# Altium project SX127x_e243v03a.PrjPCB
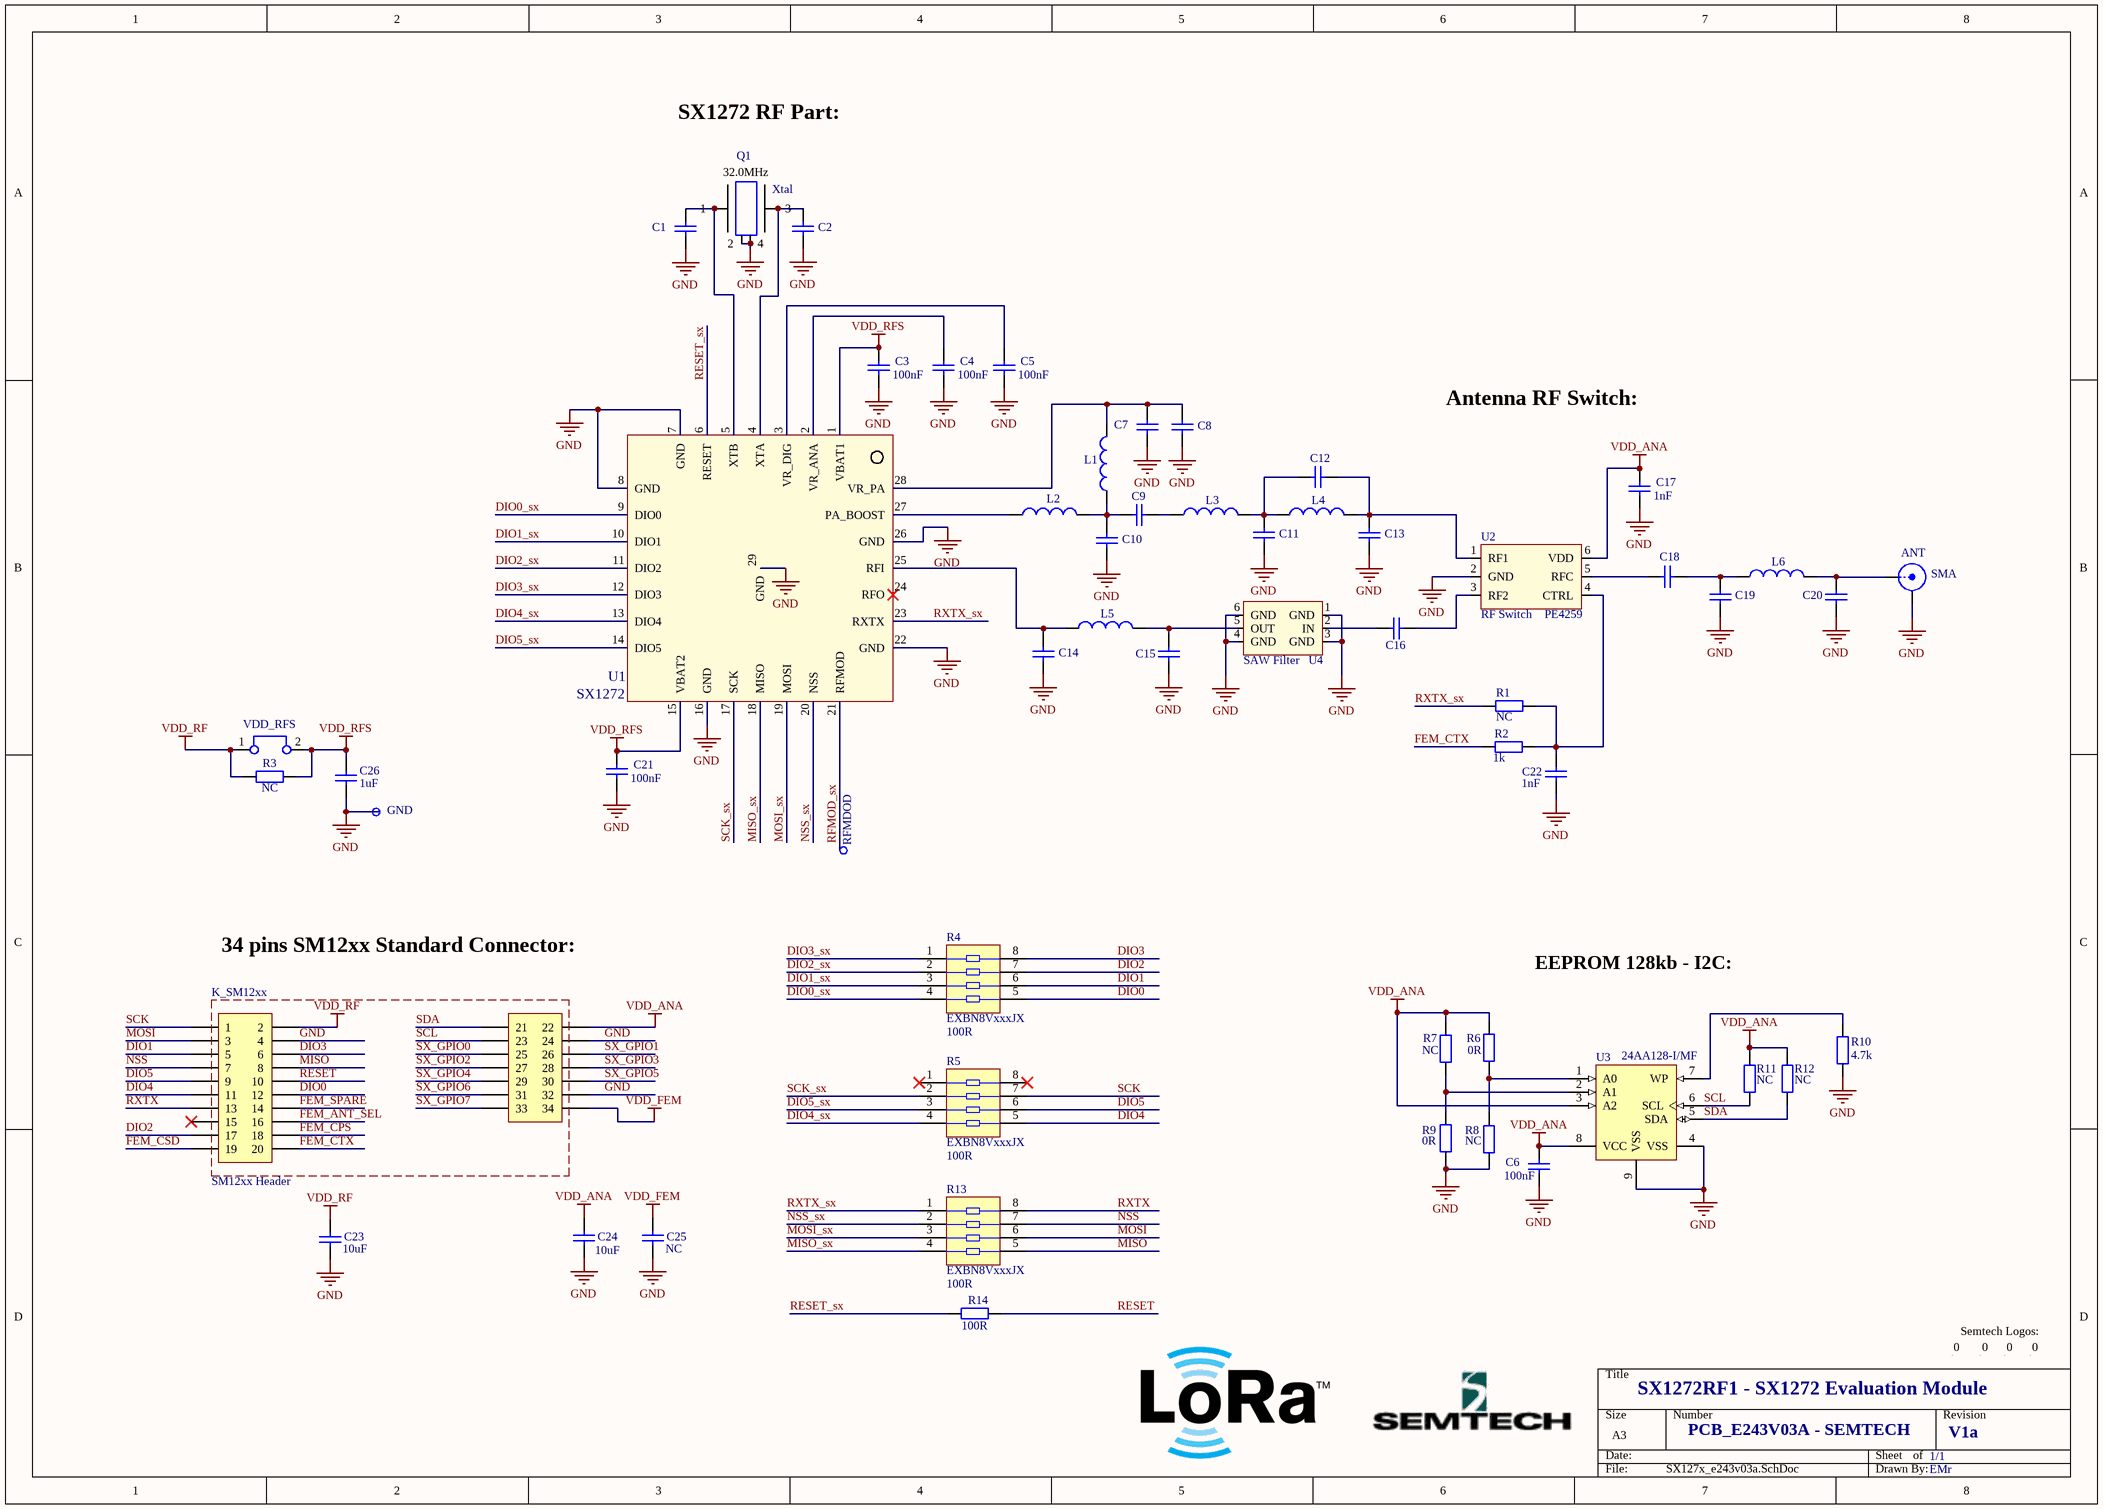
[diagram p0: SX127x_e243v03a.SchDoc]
1 sheet, 60 parts. Net scope: global (net labels, ports and power ports of the same name join across sheets).
Board file: SX127x_e243v03a.PcbDoc

## Sheet SX127x_e243v03a.SchDoc
size A3

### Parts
ANT  SMA  [SMA END LAUNCH JACK RECEPTACLE SHORT]
C1  Cap  [rlc_402_smd]  (value not drawn)
C2  Cap  [rlc_402_smd]  (value not drawn)
C3  value 100nF  [rlc_402_smd]  (hidden comment: Cap)
C4  value 100nF  [rlc_402_smd]  (hidden comment: Cap)
C5  value 100nF  [rlc_402_smd]  (hidden comment: Cap)
C6  value 100nF  [rlc_402_smd]  (hidden comment: Cap)
C7  Cap  [rlc_402_smd]  (value not drawn)
C8  Cap  [rlc_402_smd]  (value not drawn)
C9  Cap  [rlc_402_smd]  (value not drawn)
C10  Cap  [rlc_402_smd]  (value not drawn)
C11  Cap  [rlc_402_smd]  (value not drawn)
C12  Cap  [rlc_402_smd]  (value not drawn)
C13  Cap  [rlc_402_smd]  (value not drawn)
C14  Cap  [rlc_402_smd]  (value not drawn)
C15  Cap  [rlc_402_smd]  (value not drawn)
C16  Cap  [rlc_402_smd]  (value not drawn)
C17  value 1nF  [rlc_402_smd]  (hidden comment: Cap)
C18  Cap  [rlc_402_smd]  (value not drawn)
C19  Cap  [rlc_402_smd]  (value not drawn)
C20  Cap  [rlc_402_smd]  (value not drawn)
C21  value 100nF  [rlc_402_smd]  (hidden comment: Cap)
C22  value 1nF  [rlc_402_smd]  (hidden comment: Cap)
C23  value 10uF  [rlc_805_smd]  (hidden comment: Cap)
C24  value 10uF  [rlc_805_smd]  (hidden comment: Cap)
C25  value NC  [rlc_805_smd]  (hidden comment: Cap)
C26  value 1uF  [rlc_603_smd]  (hidden comment: Cap Semi)
GND  Test Pin  [pin_1mm]  (value not drawn)
K_SM12xx  SM12xx Header  [HDR34 Header]
L1  Inductor  [rlc_402_smd]  (value not drawn)
L2  Inductor  [rlc_402_smd]  (value not drawn)
L3  Inductor  [rlc_402_smd]  (value not drawn)
L4  Inductor  [rlc_402_smd]  (value not drawn)
L5  Inductor  [rlc_402_smd]  (value not drawn)
L6  Inductor  [rlc_402_smd]  (value not drawn)
Logo_Bot  Logo symbol  [logo_semtech_horiz_size3]  (value not drawn)
Logo_Lora_Bot  Logo symbol  [Logo LoRa Size4]  (value not drawn)
Logo_Lora_Top  Logo symbol  [Logo LoRa Size2]  (value not drawn)
Logo_Top  Logo symbol  [logo_semtech_horiz_size2]  (value not drawn)
Q1  Xtal  value 32.0MHz  [nd3225da - nd2520da]
R1  value NC  [rlc_402_smd]  (hidden comment: Resistor)
R2  value 1k  [rlc_402_smd]  (hidden comment: Resistor)
R3  value NC  [rlc_805_smd]  (hidden comment: Resistor)
R4  EXBN8VxxxJX  value 100R  [EXB28V]
R5  EXBN8VxxxJX  value 100R  [EXB28V]
R6  value 0R  [rlc_402_smd]  (hidden comment: Resistor)
R7  value NC  [rlc_402_smd]  (hidden comment: Resistor)
R8  value NC  [rlc_402_smd]  (hidden comment: Resistor)
R9  value 0R  [rlc_402_smd]  (hidden comment: Resistor)
R10  value 4.7k  [rlc_402_smd]  (hidden comment: Resistor)
R11  value NC  [rlc_402_smd]  (hidden comment: Resistor)
R12  value NC  [rlc_402_smd]  (hidden comment: Resistor)
R13  EXBN8VxxxJX  value 100R  [EXB28V]
R14  value 100R  [rlc_402_smd]  (hidden comment: Resistor)
RFMDOD  Test Pin  [pin_0.9mm]  (value not drawn)
U1  SX1272  [vqfn28_6x6mm]
U2  RF Switch  value PE4259  [SC70-6]
U3  24AA128-I/MF  [DFN8_ 5x6mm]
U4  SAW Filter  [DCC6C_3.0x3.0mm]
VDD_RFS  Jumper  [bridge_254mm]  (value not drawn)

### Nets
GND: ANT.2(GND) C1.1 C2.1 C3.1 C4.1 C5.1 C6.1 C7.1 C8.1 C10.1 C11.1 C13.1 C14.1 C15.1 C17.1 C19.1 C20.1 C21.1 C22.2 C23.1 C24.1 C25.2 C26.1 GND.1(pin) K_SM12xx.4 K_SM12xx.24 K_SM12xx.32 Q1.2 Q1.4 R8.1 R9.1 R10.1 U1.7(GND) U1.8(GND) U1.16(GND) U1.22(GND) U1.26(GND) U1.29(GND) U2.2(GND) U3.4(VSS) U3.9(VSS) U4.1(GND) U4.3(GND) U4.4(GND) U4.6(GND)
VDD_ANA: C6.2 C17.2 C24.2 K_SM12xx.22 R6.2 R7.2 R11.2 R12.2 U2.6(VDD) U3.3(A2) U3.8(VCC)
VDD_FEM: C25.1 K_SM12xx.34
VDD_RF: C23.2 K_SM12xx.2 R3.2 VDD_RFS.1
VDD_RFS: C3.2 C21.2 C26.2 R3.1 U1.1(VBAT1) U1.15(VBAT2) VDD_RFS.2
DIO0: K_SM12xx.12 R4.5
DIO0_sx: R4.4 U1.9(DIO0)
DIO1: K_SM12xx.5 R4.6
DIO1_sx: R4.3 U1.10(DIO1)
DIO2: K_SM12xx.17 R4.7
DIO2_sx: R4.2 U1.11(DIO2)
DIO3: K_SM12xx.6 R4.8
DIO3_sx: R4.1 U1.12(DIO3)
DIO4: K_SM12xx.11 R5.5
DIO4_sx: R5.4 U1.13(DIO4)
DIO5: K_SM12xx.9 R5.6
DIO5_sx: R5.3 U1.14(DIO5)
FEM_ANT_SEL: K_SM12xx.16
FEM_CPS: K_SM12xx.18
FEM_CSD: K_SM12xx.19
FEM_CTX: K_SM12xx.20 R2.2
FEM_SPARE: K_SM12xx.14
MISO: K_SM12xx.8 R13.5
MISO_sx: R13.4 U1.18(MISO)
MOSI: K_SM12xx.3 R13.6
MOSI_sx: R13.3 U1.19(MOSI)
NSS: K_SM12xx.7 R13.7
NSS_sx: R13.2 U1.20(NSS)
RESET: K_SM12xx.10 R14.2
RESET_sx: R14.1 U1.6(RESET)
RFMOD_sx: RFMDOD.1(pin) U1.21(RFMOD)
RXTX: K_SM12xx.13 R13.8
RXTX_sx: R1.1 R13.1 U1.23(RXTX)
SCK: K_SM12xx.1 R5.7
SCK_sx: R5.2 U1.17(SCK)
SCL: K_SM12xx.23 R11.1 U3.6(SCL)
SDA: K_SM12xx.21 R12.1 U3.5(SDA)
SX_GPIO0: K_SM12xx.25
SX_GPIO1: K_SM12xx.26
SX_GPIO2: K_SM12xx.27
SX_GPIO3: K_SM12xx.28
SX_GPIO4: K_SM12xx.29
SX_GPIO5: K_SM12xx.30
SX_GPIO6: K_SM12xx.31
SX_GPIO7: K_SM12xx.33
NetANT_1: ANT.1(Signal) C20.2 L6.2
NetC1_2: C1.2 Q1.1 U1.5(XTB)
NetC2_2: C2.2 Q1.3 U1.4(XTA)
NetC4_2: C4.2 U1.2(VR_ANA)
NetC5_2: C5.2 U1.3(VR_DIG)
NetC7_2: C7.2 C8.2 L1.2 U1.28(VR_PA)
NetC9_1: C9.1 L3.1
NetC9_2: C9.2 C10.2 L1.1 L2.2
NetC11_2: C11.2 C12.2 L3.2 L4.1
NetC12_1: C12.1 C13.2 L4.2 U2.1(RF1)
NetC14_2: C14.2 L5.1 U1.25(RFI)
NetC15_2: C15.2 L5.2 U4.5(OUT)
NetC16_1: C16.1 U2.3(RF2)
NetC16_2: C16.2 U4.2(IN)
NetC18_1: C18.1 C19.2 L6.1
NetC18_2: C18.2 U2.5(RFC)
NetC22_1: C22.1 R1.2 R2.1 U2.4(CTRL)
NetL2_1: L2.1 U1.27(PA_BOOST)
NetR6_1: R6.1 R8.2 U3.1(A0)
NetR7_1: R7.1 R9.2 U3.2(A1)
NetR10_2: R10.2 U3.7(WP)

Not connected (* = marked no-connect by the designer): K_SM12xx 15*; Logo_Bot 0; Logo_Lora_Bot 0; Logo_Lora_Top 0; Logo_Top 0; R5 1* 8*; U1 24(RFO)*

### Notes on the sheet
- SX1272 RF Part:
- Antenna RF Switch:
- 34 pins SM12xx Standard Connector:
- EEPROM 128kb - I2C:
- SX1272RF1 - SX1272 Evaluation Module
- Semtech Logos:
- PCB_E243V03A - SEMTECH
- 1/1
- V1a
- EMr

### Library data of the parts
ANT = SMA: SMA Straight Connector
C1 = Cap: Capacitor SMD; Value: 18pnF
C2 = Cap: Capacitor SMD; Value: 18pF
C3-C6 C17 C21-C25 = Cap: Capacitor SMD
C7-C16 C18 = Cap: Capacitor SMD; Value: 100nF
C19 C20 = Cap: Capacitor SMD; Value: NC
C26 = Cap Semi: Capacitor (Semiconductor SIM Model)
GND RFMDOD = test_pin
K_SM12xx = SM12xx Header: SM12xx Header; 34pins: 2x10pins + 2x7pins
L1-L5 = Inductor: Inductor SMD; Code_IEC: 1005; Value: VAL?
L6 = Inductor: Inductor SMD; Code_IEC: 1005; Value: 0R
Logo_Bot Logo_Lora_Bot Logo_Lora_Top Logo_Top = Logo: Schematic symbol for Logo
Q1 = Xtal GND: Crystal with GND pins
R1-R3 R6-R12 R14 = Resistor: Resistor SMD - IEC symbol version
R4 R5 R13 = EXBN8VxxxJX: Mini-Flat Package, Isolated Resistor Network, 0.031 W/resistor
U1 = SX1272: SX1272 - Low Power Integrated UHF Transceiver with Lora technology
U2 = PE4259 RF Switch: PE4259 Peregrine RF Switch
U3 = 24AA128-I/MF: 128kbit, 400kHz, 1.7V, 8-Pin DFN, Industrial Temperature
U4 = SAW Filter: SAW Filter - Bandpass - TEMEX type
VDD_RFS = Jumper: Jumper Wire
